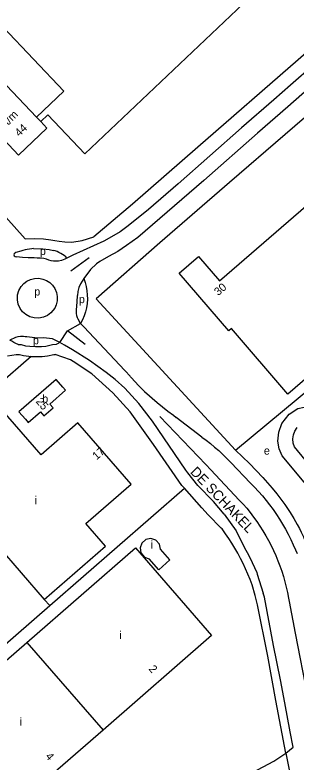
# Model space of a CAD drawing. Extents: x 156097 to 158136, y 385644 to 388348.
# Drawn here: x 156664.4 to 156805, y 386788.5 to 387161.9 of the extents above; entities that cross this region are included whole.
import ezdxf

# ---------------------------------------------------------------- set-up
doc = ezdxf.new("R2010")
doc.units = 0
for name, color, linetype in [('BLT_Basislijn', 7, 'Continuous'), ('BLT_Bebouwing', 7, 'Continuous'), ('BLT_Centroide', 7, 'Continuous'), ('BLT_Huisnummer', 7, 'Continuous'), ('BLT_Huisnummer_reeks', 7, 'Continuous'), ('BLT_Onderverdeling_panden', 7, 'Continuous'), ('BLT_Straatnaam', 7, 'Continuous'), ('BLT_Vlakafsluiter', 7, 'Continuous')]:
    doc.layers.add(name, color=color, linetype=linetype)

msp = doc.modelspace()

# ---------------------------------------------------------------- linework, layer by layer
at = {"layer": 'BLT_Basislijn'}
for p, q in [((156630.73, 387093), (156669.52, 387050.04)), ((156701.56, 387040.5), (156692.32, 387033.88)), ((156699.56, 386997.12), (156690.74, 387004.06)), ((156672.56, 386991.26), (156589.57, 386919.01)), ((156774.73, 386944.4), (156815.18, 386977.97)), ((156757.9, 386950.88), (156745.14, 386960.77)), ((156772.38, 386938.18), (156782.29, 386927.92)), ((156776.64, 386919.47), (156762.48, 386934.48)), ((156681.8, 386866.68), (156749.19, 386925.33)), ((156769.13, 386912.43), (156763.66, 386918.72)), ((156785.65, 386882.46), (156788.6, 386872.83)), ((156679.1, 386869.78), (156681.8, 386866.68)), ((156801.58, 386868.79), (156804.6, 386852.91)), ((156655.27, 386843.61), (156681.8, 386866.68))]:
    msp.add_line(p, q, dxfattribs=at)
for points in [[(156893.26, 387224.91), (156873.19, 387200.58), (156856.27, 387183.3), (156755.91, 387095.83), (156723.24, 387067.35)], [(156864.97, 387181.9), (156848.92, 387167.6), (156837.62, 387157.69), (156825.29, 387146.9), (156814.07, 387137.11), (156802.3, 387126.83), (156793.93, 387119.55), (156777.79, 387105.45), (156745.99, 387077.54), (156731.26, 387064.74), (156721.13, 387056.5)], [(156863.05, 387170.42), (156852.77, 387161.4), (156838.58, 387148.96), (156825.26, 387137.32), (156812.08, 387125.81), (156800.89, 387116.05), (156785.71, 387102.82), (156758.85, 387079.25), (156725.94, 387050.64), (156720.21, 387046.65), (156715.83, 387043.74), (156711.3, 387041.11), (156706.96, 387038.65), (156705.27, 387037.53), (156702.15, 387034.61), (156698.86, 387030.12)], [(156851.67, 387147.13), (156827.43, 387126.2), (156771.74, 387078.1), (156736.88, 387048.01), (156705.02, 387020), (156774.73, 386944.4)], [(156723.24, 387067.35), (156703.86, 387051.04)], [(156721.13, 387056.5), (156716.98, 387053.58), (156712.78, 387050.95), (156708.83, 387048.84), (156693.33, 387041.79), (156690.3, 387040.39)], [(156669.52, 387050.04), (156674.01, 387050.11), (156678.79, 387050.01), (156682.32, 387049.57), (156684.33, 387049.24)], [(156684.33, 387049.24), (156686.52, 387048.88), (156689.33, 387048.54), (156692.84, 387048.42), (156697.97, 387049.19), (156703.86, 387051.04)], [(156664.8, 387043.16), (156664.03, 387042.52), (156663.8, 387042.02), (156664.04, 387041.49), (156664.59, 387041.19), (156665.28, 387041.02)], [(156673.69, 387045.12), (156672.84, 387045.04), (156671.73, 387044.89), (156670.62, 387044.7), (156669.52, 387044.47), (156668.44, 387044.2), (156667.37, 387043.89), (156664.8, 387043.16)], [(156673.69, 387045.12), (156678.42, 387045.02), (156681.6, 387044.62), (156683.75, 387044.27)], [(156690.3, 387040.39), (156689.86, 387041.02), (156689.05, 387041.63), (156688.21, 387042.2), (156687.33, 387042.73), (156686.42, 387043.21), (156685.49, 387043.64), (156684.53, 387044.01), (156683.75, 387044.27)], [(156690.3, 387040.39), (156689.3, 387039.93), (156688.53, 387039.56), (156687.77, 387039.27), (156686.29, 387038.93), (156684.95, 387038.81), (156683.7, 387038.89), (156682.5, 387039.1), (156681.45, 387039.44), (156680.24, 387039.8), (156678.92, 387040.11), (156677.1, 387040.34), (156675.51, 387040.42), (156673.96, 387040.5), (156671.03, 387040.58), (156668.21, 387040.71), (156665.28, 387041.02)], [(156684.3, 387015.35), (156682.41, 387012.98), (156680.72, 387011.73), (156678.68, 387010.81), (156676.4, 387010.36), (156674.04, 387010.46), (156671.8, 387011.1), (156669.84, 387012.18), (156668.26, 387013.57), (156667.01, 387015.26), (156666.1, 387017.3), (156665.65, 387019.59), (156665.75, 387021.95), (156666.39, 387024.18), (156667.48, 387026.14), (156668.87, 387027.72)], [(156668.87, 387027.72), (156670.4, 387028.87), (156672.22, 387029.74), (156674.24, 387030.24), (156676.35, 387030.31), (156678.4, 387029.94), (156680.27, 387029.18), (156681.88, 387028.14), (156683.25, 387026.8), (156684.39, 387025.14), (156685.2, 387023.21), (156685.59, 387021.14), (156685.54, 387019.06), (156685.09, 387017.09), (156684.3, 387015.35)], [(156698.86, 387030.12), (156697.21, 387027.5), (156696.36, 387025.65), (156695.9, 387023.73), (156695.64, 387021.76)], [(156698.86, 387030.12), (156699.53, 387028.18), (156700.06, 387026.16), (156700.42, 387024.09), (156700.62, 387021.97), (156700.64, 387019.84), (156700.49, 387017.71), (156700.17, 387015.6), (156699.67, 387013.53), (156699.01, 387011.53), (156698.21, 387009.61), (156697.27, 387007.78)], [(156697.27, 387007.78), (156696.08, 387009.82), (156695.77, 387010.59), (156695.45, 387011.51), (156695.21, 387012.94), (156695.17, 387014.31), (156695.55, 387018.51), (156695.64, 387021.76)], [(156726.3, 386976.75), (156722.78, 386980.5), (156722.52, 386980.78), (156722.26, 386981.06), (156722, 386981.34), (156721.74, 386981.63), (156719.96, 386983.63), (156719.46, 386984.22), (156698.84, 387006.07), (156698.59, 387006.37), (156697.27, 387007.78)], [(156686.86, 386998.15), (156683.28, 387000), (156678.76, 387000.58), (156675.77, 387000.36), (156670.41, 387000.97), (156669.51, 387001.11), (156668.71, 387001.19), (156667.97, 387001.22), (156667.26, 387001.21), (156665.89, 387001.02), (156664.75, 387000.73), (156661.95, 386999.4)], [(156666.09, 386997.22), (156664.93, 386997.74), (156663.91, 386998.25), (156662.91, 386998.8), (156661.95, 386999.4)], [(156686.86, 386998.15), (156685.77, 386997.59), (156685.19, 386997.33)], [(156733.16, 386958.82), (156726.45, 386967.68), (156719.44, 386975.31), (156714.51, 386979.75), (156710.1, 386983.24), (156701.75, 386989.26), (156693.14, 386994.6), (156689.2, 386996.93), (156686.86, 386998.15)], [(156666.09, 386997.22), (156667.49, 386997.18), (156669.69, 386996.6), (156671.88, 386996.29), (156674.63, 386996.18), (156677.78, 386996.18), (156679.87, 386996.45), (156683.22, 386997.19), (156685.19, 386997.33)], [(156660.72, 386991.51), (156664.96, 386992.26), (156666.77, 386992.2), (156668.7, 386991.69), (156671.43, 386991.3), (156672.56, 386991.26)], [(156672.56, 386991.26), (156674.53, 386991.18), (156678.09, 386991.18), (156680.73, 386991.51), (156683.94, 386992.23), (156684.51, 386992.27)], [(156733.67, 386947.23), (156722.05, 386963.6), (156713.43, 386973.09), (156702.87, 386982.46), (156693.62, 386988.7), (156692.18, 386989.46), (156684.51, 386992.27)], [(156726.3, 386976.75), (156729.23, 386973.69), (156735.61, 386968.21), (156738.26, 386966.02), (156740.95, 386963.89), (156743.69, 386961.83), (156745.14, 386960.77)], [(156812.61, 386891.32), (156818.74, 386893.28), (156827.29, 386900.29), (156828.4, 386903.38), (156827.35, 386906.33), (156798.15, 386941.62), (156796.57, 386945.02), (156795.88, 386948.8), (156796.34, 386953.38), (156798, 386957.66), (156801.65, 386962.4), (156805.97, 386965.18), (156812.2, 386966.59), (156819.25, 386973.04), (156815.18, 386977.97)], [(156736.88, 386961.21), (156759.92, 386937.18), (156762.48, 386934.48)], [(156763.66, 386918.72), (156755.95, 386926.77), (156750.87, 386933.07), (156749.86, 386934.35), (156733.16, 386958.82)], [(156832.58, 386911.54), (156804.18, 386945.97), (156803.62, 386947.94), (156803.47, 386949.99), (156803.73, 386952.02), (156804.48, 386953.92), (156805.59, 386955.65)], [(156757.9, 386950.88), (156760.09, 386949.3), (156762.22, 386947.65), (156764.3, 386945.93), (156766.33, 386944.16), (156768.31, 386942.33), (156770.23, 386940.43), (156772.1, 386938.49), (156772.38, 386938.18)], [(156749.19, 386925.33), (156747.97, 386926.7), (156733.67, 386947.23)], [(156774.73, 386944.4), (156781.71, 386937.68), (156788.34, 386930.67), (156793.1, 386925.47), (156795.49, 386922.57), (156797.47, 386919.94), (156799.46, 386917.18), (156802.08, 386913.26), (156803.97, 386910.17), (156805.59, 386907.22), (156806.69, 386905.15), (156807.57, 386903.4), (156808.72, 386901), (156809.5, 386899.2), (156810.61, 386896.67), (156811.35, 386894.78), (156812.27, 386892.29), (156812.61, 386891.32)], [(156782.29, 386927.92), (156784.31, 386925.85), (156786.27, 386923.72), (156788.18, 386921.53), (156790.02, 386919.3), (156791.81, 386917.01), (156793.52, 386914.68), (156795.18, 386912.3), (156796.76, 386909.87), (156798.28, 386907.4), (156799.73, 386904.9), (156801.11, 386902.35), (156802.42, 386899.76), (156803.66, 386897.14), (156804.82, 386894.49), (156805.57, 386892.68)], [(156799.99, 386792.99), (156794.9, 386819.22), (156790.84, 386841.41), (156785.79, 386867.05), (156784.5, 386871.72), (156783.08, 386876.99), (156782.06, 386879.71), (156780.98, 386882.4), (156779.82, 386885.06), (156778.58, 386887.69), (156777.28, 386890.28), (156775.9, 386892.83), (156774.46, 386895.35), (156772.94, 386897.82), (156771.36, 386900.26), (156769.71, 386902.64), (156768, 386904.98), (156767.63, 386905.47), (156761.05, 386912.08), (156757.83, 386915.61), (156749.19, 386925.33)], [(156776.64, 386919.47), (156778.51, 386917.42), (156780.33, 386915.31), (156782.08, 386913.15), (156783.77, 386910.94), (156785.4, 386908.68), (156786.96, 386906.38), (156788.45, 386904.03), (156789.87, 386901.64), (156791.23, 386899.21), (156792.52, 386896.74), (156793.73, 386894.24), (156794.87, 386891.71), (156795.94, 386889.14), (156796.93, 386886.54), (156797.85, 386883.91), (156798.69, 386881.26), (156799.46, 386878.59), (156800.15, 386875.89), (156800.76, 386873.18), (156801.29, 386870.45), (156801.58, 386868.79)], [(156769.13, 386912.43), (156775.12, 386904.07), (156779.24, 386895.59), (156780.61, 386893.18), (156781.91, 386890.72), (156783.13, 386888.23), (156784.29, 386885.71), (156785.37, 386883.15), (156785.65, 386882.46)], [(156799.99, 386792.99), (156803.53, 386795.93), (156802.12, 386803.52), (156799.46, 386818.11), (156797.24, 386829.58), (156793.79, 386846.71), (156789.24, 386870.87), (156788.6, 386872.83)], [(156804.6, 386852.91), (156810.79, 386821.2), (156815.84, 386795.93)], [(156502.11, 386680.86), (156596.09, 386624.12), (156600.79, 386622.53), (156605.37, 386622.68), (156609.01, 386624.13), (156613.02, 386628.11), (156667.39, 386713.69), (156672.33, 386720.54), (156678.4, 386728.06), (156684.78, 386734.14), (156691.78, 386740.26), (156725.55, 386766), (156731.56, 386769.96), (156736.32, 386772.34), (156742.41, 386774.64), (156748.29, 386775.96), (156771.61, 386780.02), (156783.21, 386783.33), (156793.87, 386788.99), (156799.99, 386793)]]:
    msp.add_lwpolyline(points, dxfattribs=at)
at = {"layer": 'BLT_Bebouwing'}
for p, q in [((156741.94, 386889.5), (156737.21, 386894.93)), ((156736.35, 386884.64), (156731.63, 386890.07)), ((156741.94, 386889.5), (156736.35, 386884.64))]:
    msp.add_line(p, q, dxfattribs=at)
for points in [[(156675.18, 387110.78), (156688.92, 387123.81), (156643.21, 387171.93), (156634.48, 387163.64), (156596.48, 387203.63), (156592.42, 387199.76), (156590.88, 387200.02)], [(156790.45, 387167.87), (156784.89, 387173.71), (156699.41, 387092.47)], [(156648.81, 387110.19), (156631.08, 387128.84), (156645.2, 387142.29), (156675.18, 387110.78)], [(156800.99, 386972.36), (156772.74, 387005.15), (156771.43, 387004.01), (156746.54, 387032.81), (156756.3, 387041.25), (156766.82, 387029.07), (156869.16, 387117.49)], [(156869.16, 387117.49), (156912.02, 387068.17), (156800.99, 386972.36)], [(156677.31, 387108.61), (156680.37, 387105.35), (156666.21, 387091.89), (156648.81, 387110.19)], [(156699.41, 387092.47), (156680.9, 387111.99), (156677.31, 387108.61)], [(156685.07, 386979.71), (156666.43, 386963.59), (156669.71, 386959.8), (156671.11, 386958.18)], [(156689.73, 386974.32), (156688.34, 386975.93), (156685.07, 386979.71)], [(156671.11, 386958.18), (156677.29, 386963.52), (156678.94, 386961.6), (156683.48, 386965.53), (156681.81, 386967.46), (156689.73, 386974.32)], [(156677.56, 386942.05), (156657.59, 386965), (156624.47, 386936.16)], [(156722.5, 386927.39), (156695.88, 386957.98), (156677.56, 386942.05)], [(156679.1, 386869.78), (156709.71, 386896.41), (156699.85, 386907.73), (156722.5, 386927.39)], [(156632.81, 386922.98), (156679.1, 386869.78)], [(156737.21, 386894.93), (156736.68, 386897.42), (156734.85, 386899.45), (156732.42, 386900.24), (156729.92, 386899.75), (156727.86, 386897.96), (156727.03, 386895.55), (156727.47, 386893.03), (156729.23, 386890.94), (156731.63, 386890.07)], [(156670.35, 386848.28), (156724.66, 386895.54), (156762.81, 386851.72), (156708.5, 386804.46)], [(156625.09, 386808.89), (156670.35, 386848.28)], [(156708.5, 386804.46), (156663.24, 386765.07)]]:
    msp.add_lwpolyline(points, dxfattribs=at)
at = {"layer": 'BLT_Onderverdeling_panden'}
for p, q in [((156675.18, 387110.78), (156677.31, 387108.61)), ((156670.35, 386848.28), (156708.5, 386804.46))]:
    msp.add_line(p, q, dxfattribs=at)
at = {"layer": 'BLT_Vlakafsluiter'}
for p, q in [((156690.74, 387004.06), (156697.27, 387007.78)), ((156686.86, 386998.15), (156690.74, 387004.06)), ((156799.99, 386793), (156805.04, 386766.42))]:
    msp.add_line(p, q, dxfattribs=at)

# ---------------------------------------------------------------- texts
at = {"layer": 'BLT_Centroide'}
for s, p in [('p', (156676.89, 387041.92)), ('p', (156674.11, 387021.7)), ('p', (156696.4, 387017.87)), ('p', (156673.45, 386997.34)), ('b', (156678.08, 386968.12)), ('e', (156788.95, 386942.15)), ('i', (156674.33, 386917.38)), ('i', (156732.31, 386895.17)), ('i', (156716.58, 386850)), ('i', (156666.79, 386806.69))]:
    msp.add_text(s, height=4, dxfattribs=at).set_placement(p)
at = {"layer": 'BLT_Huisnummer'}
for s, rotation, p in [('30', 40.8317, (156766.13, 387021.37)), ('25', 310.8711, (156674.62, 386968.57)), ('2', 311.0418, (156731.09, 386834.88)), ('4', 311.0418, (156679.44, 386791.17))]:
    msp.add_text(s, height=4, rotation=rotation, dxfattribs=at).set_placement(p)
at = {"layer": 'BLT_Huisnummer_reeks'}
for s, rotation, p in [('t/m', 44.8863, (156661.01, 387106.53)), ('44', 43.5549, (156666.59, 387100.9)), ('17', 41.0252, (156705.27, 386939.27))]:
    msp.add_text(s, height=4, rotation=rotation, dxfattribs=at).set_placement(p)
at = {"layer": 'BLT_Straatnaam'}
msp.add_text('DE SCHAKEL', height=5, rotation=313.6131, dxfattribs=at).set_placement((156751.79, 386933.23))

doc.saveas('drawing.dxf')
